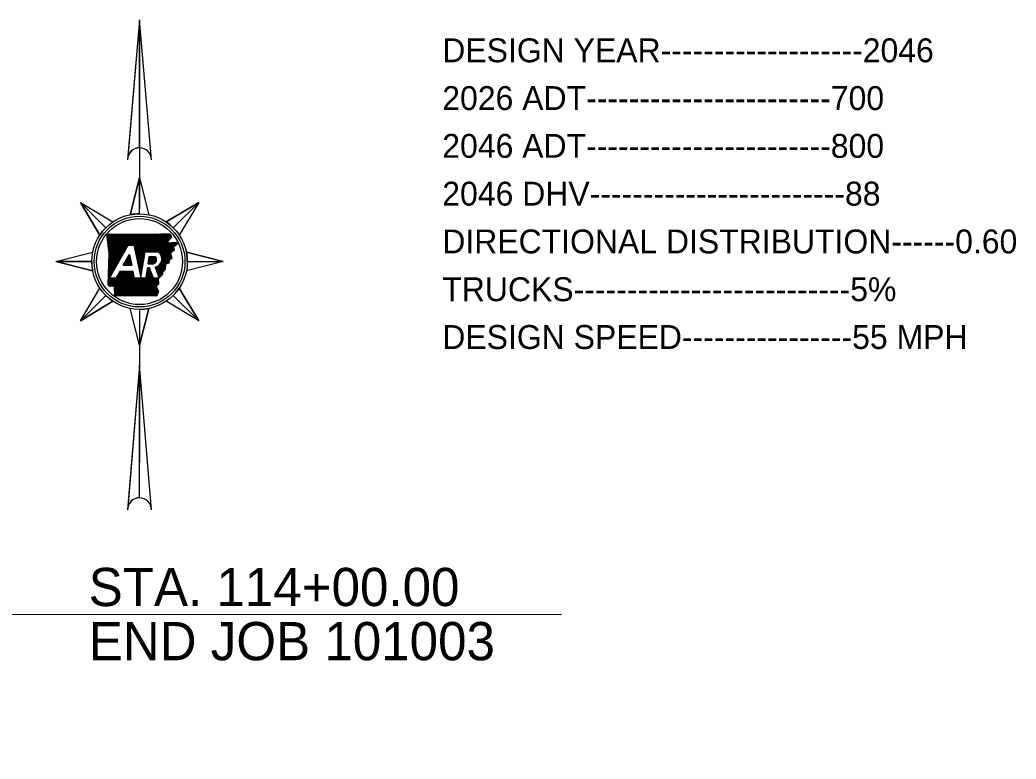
# Model space of a CAD drawing. Extents: x 152 to 3426, y 67 to 2142.
# Drawn here: x 2447 to 3073, y 714 to 1178 of the extents above; entities that cross this region are included whole.
import ezdxf

# ---------------------------------------------------------------- set-up
doc = ezdxf.new("R2010")
doc.units = 0
for name, color, linetype in [('Default', 7, 'Continuous'), ('R_Draft', 7, 'Continuous'), ('S_AREA_CALC', 7, 'Continuous')]:
    doc.layers.add(name, color=color, linetype=linetype)

msp = doc.modelspace()

# ---------------------------------------------------------------- linework, layer by layer
at = {"layer": 'Default'}
msp.add_lwpolyline([(1791.62, 713.9), (2261.79, 804.87), (2787.22, 804.61)], dxfattribs=at)
at = {"layer": 'R_Draft'}
for p, q in [((2522.22, 1177.93), (2514.83, 1091.46)), ((2522.22, 1177.93), (2522.22, 1059.5)), ((2522.22, 1097.68), (2522.22, 1177.93)), ((2514.93, 1092.66), (2515.27, 1093)), ((2514.97, 1093.13), (2515.66, 1093.81)), ((2522.22, 1078.72), (2516.38, 1055.65)), ((2522.22, 1056.22), (2522.22, 1078.72)), ((2485.1, 1063.35), (2501.01, 1047.44)), ((2501.01, 1047.44), (2485.1, 1063.35)), ((2485.1, 1063.35), (2497.28, 1042.9)), ((2559.35, 1063.35), (2538.9, 1051.16)), ((2543.44, 1047.44), (2559.35, 1063.35)), ((2543.44, 1047.44), (2559.35, 1063.35)), ((2501.77, 1043.13), (2502.04, 1043.4)), ((2501.87, 1042.38), (2502.89, 1043.4)), ((2501.96, 1041.62), (2503.73, 1043.39)), ((2502.06, 1040.87), (2504.58, 1043.39)), ((2502.15, 1040.11), (2505.43, 1043.39)), ((2502.24, 1039.36), (2506.28, 1043.39)), ((2502.34, 1038.6), (2507.13, 1043.39)), ((2502.43, 1037.85), (2507.97, 1043.39)), ((2502.53, 1037.09), (2508.82, 1043.39)), ((2502.62, 1036.34), (2509.67, 1043.39)), ((2502.71, 1035.59), (2510.52, 1043.39)), ((2502.81, 1034.83), (2511.37, 1043.39)), ((2502.9, 1034.08), (2512.21, 1043.39)), ((2503, 1033.32), (2513.06, 1043.39)), ((2503.02, 1024.87), (2521.56, 1043.41)), ((2503.05, 1025.74), (2520.71, 1043.4)), ((2503.08, 1026.62), (2519.86, 1043.4)), ((2503.09, 1032.57), (2513.91, 1043.39)), ((2503.11, 1027.5), (2519.01, 1043.4)), ((2503.14, 1028.38), (2518.16, 1043.4)), ((2503.17, 1029.25), (2517.31, 1043.4)), ((2503.18, 1031.81), (2514.76, 1043.39)), ((2503.2, 1030.13), (2516.46, 1043.4)), ((2503.23, 1031.01), (2515.61, 1043.39)), ((2515.62, 1036.62), (2522.42, 1043.41)), ((2516.47, 1036.62), (2523.27, 1043.41)), ((2517.32, 1036.62), (2524.12, 1043.42)), ((2518.17, 1036.62), (2524.98, 1043.43)), ((2518.7, 1036.3), (2525.85, 1043.44)), ((2518.85, 1035.6), (2526.71, 1043.46)), ((2519, 1034.9), (2527.57, 1043.47)), ((2519.15, 1034.2), (2528.43, 1043.48)), ((2519.3, 1033.5), (2529.29, 1043.5)), ((2519.45, 1032.8), (2530.15, 1043.51)), ((2519.6, 1032.1), (2531.02, 1043.52)), ((2519.75, 1031.4), (2531.88, 1043.54)), ((2519.9, 1030.71), (2532.74, 1043.55)), ((2520.05, 1030.01), (2533.6, 1043.56)), ((2520.19, 1029.31), (2534.46, 1043.58)), ((2520.34, 1028.61), (2535.33, 1043.59)), ((2520.49, 1027.91), (2536.19, 1043.61)), ((2520.64, 1027.21), (2537.06, 1043.63)), ((2526.54, 1032.26), (2537.93, 1043.65)), ((2527.39, 1032.26), (2538.8, 1043.67)), ((2528.24, 1032.26), (2539.67, 1043.69)), ((2529.08, 1032.26), (2540.53, 1043.71)), ((2529.93, 1032.26), (2541.4, 1043.73)), ((2530.78, 1032.26), (2541.59, 1043.07)), ((2531.63, 1032.26), (2542, 1042.63)), ((2532.48, 1032.26), (2542.11, 1041.89)), ((2533.33, 1032.26), (2540.17, 1039.11)), ((2535.92, 1029.75), (2544.48, 1038.32)), ((2502.97, 1023.11), (2513.34, 1033.48)), ((2503, 1023.99), (2514.44, 1035.44)), ((2503.28, 1015.71), (2515.11, 1036.62)), ((2515.11, 1036.62), (2518.63, 1036.62)), ((2525.77, 1032.26), (2533.99, 1032.26)), ((2534.1, 1032.18), (2540.01, 1038.09)), ((2534.56, 1031.79), (2540.9, 1038.14)), ((2534.97, 1031.36), (2541.8, 1038.18)), ((2535.34, 1030.88), (2542.69, 1038.23)), ((2535.66, 1030.34), (2543.59, 1038.27)), ((2536.05, 1026.5), (2543.75, 1034.2)), ((2536.11, 1029.1), (2545.29, 1038.28)), ((2536.23, 1028.37), (2545.68, 1037.82)), ((2536.23, 1027.52), (2543.66, 1034.95)), ((2542.8, 1032.4), (2543.85, 1033.45)), ((2545.31, 1036.6), (2546.08, 1037.37)), ((2574.72, 1026.22), (2551.65, 1032.06)), ((2469.72, 1026.22), (2492.22, 1026.22)), ((2492.22, 1026.22), (2469.72, 1026.22)), ((2469.72, 1026.22), (2492.8, 1020.38)), ((2502.88, 1020.48), (2510.01, 1027.61)), ((2502.91, 1021.35), (2511.12, 1029.57)), ((2502.94, 1022.23), (2512.23, 1031.52)), ((2511.98, 1023.92), (2515.86, 1030.76)), ((2512.02, 1023.92), (2516.39, 1028.28)), ((2512.87, 1023.92), (2516.53, 1027.58)), ((2513.04, 1025.78), (2516.24, 1028.98)), ((2513.72, 1023.92), (2516.68, 1026.88)), ((2514.15, 1027.74), (2516.09, 1029.68)), ((2514.57, 1023.92), (2516.83, 1026.18)), ((2515.25, 1029.69), (2515.94, 1030.38)), ((2520.79, 1026.51), (2525.61, 1031.33)), ((2520.94, 1025.81), (2525.43, 1030.3)), ((2521.09, 1025.11), (2525.25, 1029.27)), ((2521.24, 1024.42), (2525.07, 1028.24)), ((2521.39, 1023.72), (2524.89, 1027.22)), ((2521.54, 1023.02), (2524.71, 1026.19)), ((2527.56, 1024.84), (2532.02, 1029.31)), ((2527.73, 1025.86), (2531.17, 1029.31)), ((2527.91, 1026.89), (2530.33, 1029.31)), ((2528.09, 1027.92), (2529.48, 1029.31)), ((2528.27, 1028.95), (2528.63, 1029.31)), ((2528.33, 1029.31), (2532.19, 1029.31)), ((2528.41, 1024.84), (2532.49, 1028.93)), ((2529.26, 1024.84), (2532.78, 1028.37)), ((2530.1, 1024.84), (2532.94, 1027.68)), ((2530.95, 1024.84), (2532.87, 1026.76)), ((2532.55, 1021.3), (2541.96, 1030.7)), ((2532.78, 1020.68), (2542.12, 1030.02)), ((2533.01, 1020.06), (2542.27, 1029.33)), ((2533.24, 1019.44), (2542.43, 1028.64)), ((2535.31, 1024.91), (2541.8, 1031.39)), ((2539.53, 1024.89), (2540.72, 1026.08)), ((2552.22, 1026.22), (2574.72, 1026.22)), ((2552.22, 1026.22), (2574.72, 1026.22)), ((2502.76, 1016.97), (2505.58, 1019.79)), ((2502.79, 1017.84), (2506.69, 1021.74)), ((2502.82, 1018.72), (2507.8, 1023.7)), ((2502.85, 1019.6), (2508.91, 1025.66)), ((2502.92, 1011.18), (2511.84, 1020.1)), ((2503.42, 1010.84), (2512.68, 1020.1)), ((2504.03, 1010.6), (2513.53, 1020.1)), ((2505.04, 1010.76), (2514.38, 1020.1)), ((2505.9, 1010.77), (2515.23, 1020.1)), ((2506.57, 1010.59), (2516.08, 1020.1)), ((2506.59, 1009.77), (2516.93, 1020.1)), ((2506.6, 1008.92), (2517.77, 1020.1)), ((2506.6, 1008.07), (2518.22, 1019.7)), ((2509.82, 1020.1), (2507.34, 1015.71)), ((2508.3, 1017.41), (2510.99, 1020.1)), ((2509.41, 1019.37), (2510.14, 1020.1)), ((2518.14, 1020.1), (2509.82, 1020.1)), ((2511.98, 1023.92), (2517.32, 1023.92)), ((2515.42, 1023.92), (2516.98, 1025.48)), ((2516.27, 1023.92), (2517.13, 1024.78)), ((2517.12, 1023.92), (2517.28, 1024.09)), ((2521.69, 1022.32), (2524.53, 1025.16)), ((2521.84, 1021.62), (2524.35, 1024.13)), ((2521.99, 1020.92), (2524.18, 1023.11)), ((2522.14, 1020.22), (2524, 1022.08)), ((2522.29, 1019.52), (2523.82, 1021.05)), ((2522.44, 1018.82), (2523.64, 1020.02)), ((2526.11, 1016.56), (2529.46, 1019.9)), ((2526.29, 1017.58), (2529.23, 1020.52)), ((2526.47, 1018.61), (2529, 1021.14)), ((2526.65, 1019.64), (2528.77, 1021.76)), ((2526.83, 1020.67), (2528.52, 1022.36)), ((2527.01, 1021.69), (2527.67, 1022.36)), ((2528.55, 1022.36), (2527.12, 1022.36)), ((2527.55, 1024.84), (2531.08, 1024.84)), ((2531, 1015.71), (2528.55, 1022.36)), ((2532.03, 1022.72), (2534.61, 1015.71)), ((2532.09, 1022.54), (2532.35, 1022.8)), ((2532.32, 1021.92), (2533.94, 1023.53)), ((2533.47, 1018.82), (2538.56, 1023.91)), ((2533.69, 1018.2), (2538.46, 1022.97)), ((2533.92, 1017.58), (2538.36, 1022.02)), ((2534.15, 1016.96), (2536.75, 1019.56)), ((2502.6, 1011.71), (2506.6, 1015.71)), ((2502.62, 1012.58), (2505.75, 1015.71)), ((2502.65, 1013.46), (2504.9, 1015.71)), ((2502.67, 1014.33), (2504.05, 1015.71)), ((2502.7, 1015.21), (2503.37, 1015.87)), ((2502.73, 1016.09), (2504.48, 1017.83)), ((2507.34, 1015.71), (2503.28, 1015.71)), ((2506.6, 1007.23), (2518.37, 1019)), ((2506.6, 1006.38), (2518.52, 1018.3)), ((2506.6, 1005.53), (2518.67, 1017.6)), ((2506.62, 1004.7), (2518.82, 1016.9)), ((2507.47, 1004.7), (2518.97, 1016.2)), ((2508.31, 1004.7), (2519.33, 1015.71)), ((2509.16, 1004.7), (2520.18, 1015.71)), ((2510.01, 1004.7), (2521.03, 1015.71)), ((2510.85, 1004.69), (2521.87, 1015.71)), ((2511.7, 1004.69), (2522.72, 1015.71)), ((2512.55, 1004.69), (2523.57, 1015.71)), ((2513.4, 1004.69), (2524.42, 1015.71)), ((2514.24, 1004.69), (2525.27, 1015.71)), ((2515.09, 1004.69), (2529.68, 1019.28)), ((2515.94, 1004.69), (2529.91, 1018.66)), ((2516.78, 1004.68), (2530.14, 1018.04)), ((2517.63, 1004.68), (2530.37, 1017.42)), ((2518.48, 1004.68), (2530.6, 1016.8)), ((2525.96, 1015.71), (2519.07, 1015.71)), ((2519.33, 1004.68), (2530.83, 1016.18)), ((2520.17, 1004.68), (2531.21, 1015.71)), ((2521.02, 1004.68), (2532.06, 1015.71)), ((2521.87, 1004.68), (2532.9, 1015.71)), ((2522.59, 1018.12), (2523.46, 1019)), ((2522.71, 1004.67), (2533.75, 1015.71)), ((2522.74, 1017.43), (2523.28, 1017.97)), ((2522.89, 1016.73), (2523.1, 1016.94)), ((2523.56, 1004.67), (2534.04, 1015.15)), ((2524.41, 1004.67), (2534.08, 1014.34)), ((2525.26, 1004.67), (2534.11, 1013.53)), ((2534.61, 1015.71), (2531, 1015.71)), ((2534.38, 1016.34), (2536.39, 1018.35)), ((2526.1, 1004.67), (2534.15, 1012.72)), ((2526.95, 1004.67), (2532.76, 1010.47)), ((2527.8, 1004.67), (2533.02, 1009.89)), ((2528.64, 1004.66), (2533.28, 1009.3)), ((2529.49, 1004.66), (2533.54, 1008.72)), ((2530.34, 1004.66), (2533.81, 1008.13)), ((2531.19, 1004.66), (2534.02, 1007.5)), ((2559.35, 989.1), (2547.16, 1009.55)), ((2485.1, 989.1), (2501.01, 1005.01)), ((2501.01, 1005.01), (2485.1, 989.1)), ((2485.1, 989.1), (2505.55, 1001.28)), ((2532.03, 1004.66), (2533.64, 1006.27)), ((2532.88, 1004.66), (2533.26, 1005.03)), ((2543.44, 1005.01), (2559.35, 989.1)), ((2543.44, 1005.01), (2559.35, 989.1)), ((2522.22, 973.72), (2528.06, 996.8)), ((2522.22, 996.22), (2522.22, 996.22)), ((2522.22, 996.22), (2522.22, 900.19)), ((2522.22, 996.22), (2522.22, 973.72)), ((2522.22, 961.18), (2514.82, 871.66)), ((2522.22, 877.93), (2522.22, 961.18))]:
    msp.add_line(p, q, dxfattribs=at)
for points in [[(2529.72, 1090.18), (2522.22, 1177.93), (2514.72, 1090.18)], [(2516.38, 1055.65), (2522.22, 1078.72), (2528.06, 1055.65)], [(2497.28, 1042.9), (2485.1, 1063.35), (2505.55, 1051.16)], [(2538.9, 1051.16), (2559.35, 1063.35), (2547.16, 1042.9)], [(2501.74, 1043.4), (2513.45, 1043.39), (2523.72, 1043.41), (2535.84, 1043.6), (2541.46, 1043.73)], [(2502.59, 1011.72), (2503.24, 1031.36), (2501.74, 1043.4)], [(2545.14, 1038.35), (2546.15, 1037.29), (2543.62, 1035.22), (2543.89, 1033.12), (2541.73, 1031.69), (2542.47, 1028.47), (2540.8, 1026.95), (2540.65, 1025.29), (2538.62, 1024.56), (2538.31, 1021.43), (2536.85, 1019.87), (2536.14, 1017.52), (2534.02, 1015.58), (2534.18, 1012.14), (2532.73, 1010.53), (2534.05, 1007.58), (2533.14, 1004.66)], [(2539.72, 1038.07), (2545.21, 1038.36)], [(2492.8, 1020.38), (2469.72, 1026.22), (2492.8, 1032.06)], [(2518.63, 1036.62), (2522.98, 1016.27), (2525.77, 1032.26)], [(2551.65, 1032.06), (2574.72, 1026.22), (2551.65, 1020.38)], [(2515.86, 1030.76), (2517.32, 1023.92)], [(2527.55, 1024.84), (2528.33, 1029.31)], [(2519.07, 1015.71), (2518.14, 1020.1)], [(2527.12, 1022.36), (2525.96, 1015.71)], [(2505.55, 1001.28), (2485.1, 989.1), (2497.28, 1009.55)], [(2533.14, 1004.66), (2506.61, 1004.7), (2506.59, 1010.56)], [(2547.16, 1009.55), (2559.35, 989.1), (2538.9, 1001.28)], [(2528.06, 996.8), (2522.22, 973.72), (2516.38, 996.8)], [(2529.72, 870.43), (2522.22, 961.18), (2514.72, 870.43)]]:
    msp.add_lwpolyline(points, dxfattribs=at)
for radius in [30, 28.5, 27]:
    msp.add_circle((2522.22, 1026.22), radius, dxfattribs=at)
for centre, radius, start, end in [((2522.22, 1090.18), 7.5, 0, 180), ((2522.22, 1090.18), 7.5, 90, 170.22959), ((2522.22, 1026.22), 30, 90, 101.22909), ((2522.22, 1026.22), 30, 45, 56.22909), ((2522.22, 1026.22), 30, 135, 146.22909), ((2530.93, 1027.91), 5.31, 281.86262, 54.87052), ((2522.22, 1026.22), 30, 0, 11.22909), ((2522.22, 1026.22), 30, 180, 191.22909), ((2530.23, 1027.42), 2.72, 288.12683, 43.89016), ((2522.22, 1026.22), 30, 315, 326.22909), ((2522.22, 1026.22), 30, 225, 236.22909), ((2522.22, 1026.22), 30, 270, 281.22909), ((2522.22, 870.43), 7.5, 0, 180), ((2522.22, 870.43), 7.5, 90, 170.5511)]:
    msp.add_arc(centre, radius, start, end, dxfattribs=at)
for points in [[(2541.46, 1043.73), (2541.49, 1043.41), (2541.59, 1043.24), (2541.61, 1042.94), (2541.73, 1042.81), (2541.94, 1042.68), (2542.13, 1042.47), (2542.17, 1042.22), (2542.12, 1041.97), (2542.1, 1041.69), (2542.07, 1041.44), (2542.03, 1041.22), (2541.86, 1041.04), (2541.69, 1040.91), (2541.54, 1040.75), (2541.43, 1040.59), (2541.24, 1040.42), (2541.05, 1040.24), (2540.9, 1040.08), (2540.75, 1039.88), (2540.68, 1039.65), (2540.51, 1039.49), (2540.38, 1039.35), (2540.2, 1039.15), (2540.12, 1038.96), (2539.95, 1038.73), (2539.92, 1038.52), (2539.81, 1038.34), (2539.8, 1038.31)], [(2506.59, 1010.56), (2506.62, 1010.54), (2506.48, 1010.64), (2506.29, 1010.73), (2506.08, 1010.75), (2505.82, 1010.78), (2505.59, 1010.8), (2505.36, 1010.96), (2505.11, 1010.8), (2504.84, 1010.68), (2504.68, 1010.81), (2504.47, 1010.72), (2504.33, 1010.77), (2504.07, 1010.59), (2503.83, 1010.66), (2503.66, 1010.61), (2503.44, 1010.62), (2503.4, 1010.86), (2503.19, 1010.9), (2503.01, 1011), (2502.88, 1011.25), (2502.8, 1011.45), (2502.59, 1011.72)]]:
    msp.add_spline(points, degree=3, dxfattribs=at)

# ---------------------------------------------------------------- texts
at = {"layer": 'Default'}
for s, p in [('STA. 114+00.00', (2490.27, 809.95)), ('END JOB 101003', (2490.27, 775.95))]:
    msp.add_text(s, height=24, dxfattribs=at).set_placement(p)
at = {"layer": 'R_Draft'}
msp.add_text('DWB 7-27-17', height=0.5833, dxfattribs=at).set_placement((2520.39, 998.72))
at = {"layer": 'S_AREA_CALC'}
for s, p in [('DESIGN YEAR-------------------2046', (2712.31, 1151.36)), ('2026 ADT-----------------------700', (2712.31, 1121.36)), ('2046 ADT-----------------------800', (2712.31, 1091.36)), ('2046 DHV------------------------88', (2712.31, 1061.36)), ('DIRECTIONAL DISTRIBUTION------0.60', (2712.31, 1031.36)), ('TRUCKS--------------------------5%', (2712.31, 1001.36)), ('DESIGN SPEED----------------55 MPH', (2712.31, 971.36))]:
    msp.add_text(s, height=15, dxfattribs=at).set_placement(p)

doc.saveas('drawing.dxf')
